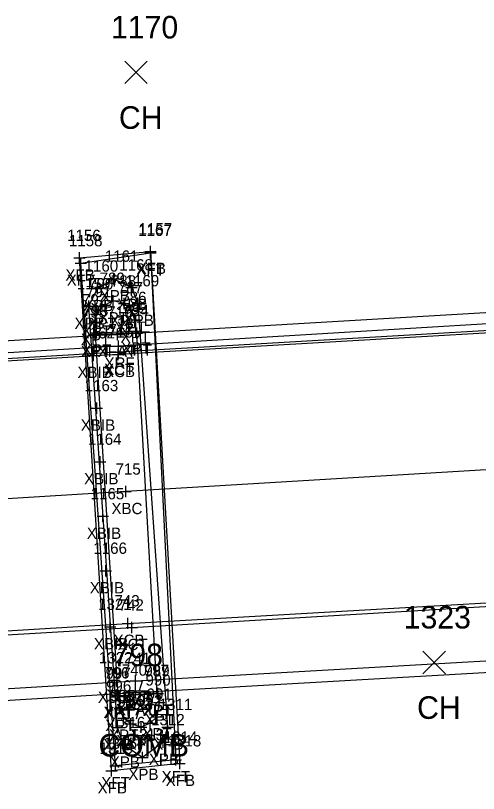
# Model space of a CAD drawing. Extents: x 1716490 to 1717645, y 888034 to 890004.
# Drawn here: x 1716987.9 to 1717028.9, y 888210.8 to 888279.7 of the extents above; entities that cross this region are included whole.
import ezdxf

# ---------------------------------------------------------------- set-up
doc = ezdxf.new("R2010")
doc.units = 0
for name, color, linetype in [('B_A', 7, 'Continuous'), ('B_I', 7, 'Continuous'), ('B_TIC', 7, 'Continuous'), ('BDC', 7, 'Continuous'), ('BELB', 7, 'Continuous'), ('BF', 7, 'Continuous'), ('BFT', 7, 'Continuous'), ('BR', 7, 'Continuous'), ('BSUBM', 7, 'Continuous'), ('L_A', 7, 'Continuous'), ('L_I', 7, 'Continuous'), ('L_TIC', 7, 'Continuous'), ('U_A', 7, 'Continuous'), ('U_I', 7, 'Continuous'), ('UP', 7, 'Continuous')]:
    doc.layers.add(name, color=color, linetype=linetype)

msp = doc.modelspace()

# ---------------------------------------------------------------- linework, layer by layer
at = {"layer": 'B_TIC'}
for p, q in [((1716993.563, 888258.21), (1716993.639, 888258.21)), ((1716999.857, 888258.656), (1716999.933, 888258.656)), ((1716999.868, 888258.793), (1716999.944, 888258.793)), ((1716993.698, 888257.744), (1716993.773, 888257.744)), ((1716996.618, 888256.374), (1716996.694, 888256.374)), ((1716995.153, 888255.5), (1716995.229, 888255.5)), ((1716998.183, 888255.6), (1716998.259, 888255.6)), ((1716996.541, 888254.414), (1716996.617, 888254.414)), ((1716997.538, 888254.168), (1716997.614, 888254.168)), ((1716998.745, 888254.197), (1716998.82, 888254.197)), ((1716994.393, 888253.93), (1716994.469, 888253.93)), ((1716995.566, 888253.926), (1716995.641, 888253.926)), ((1716998.143, 888253.584), (1716998.218, 888253.584)), ((1716995.049, 888253.239), (1716995.125, 888253.239)), ((1716998.485, 888252.722), (1716998.561, 888252.722)), ((1716994.974, 888252.512), (1716995.049, 888252.512)), ((1716994.957, 888251.44), (1716995.033, 888251.44)), ((1716995.078, 888251.568), (1716995.153, 888251.568)), ((1716996.928, 888251.433), (1716997.004, 888251.433)), ((1716998.549, 888251.731), (1716998.624, 888251.731)), ((1716998.658, 888251.565), (1716998.733, 888251.565)), ((1716997.024, 888250.409), (1716997.1, 888250.409)), ((1716994.822, 888249.583), (1716994.897, 888249.583)), ((1716997.005, 888249.663), (1716997.081, 888249.663)), ((1716997.033, 888249.858), (1716997.109, 888249.858)), ((1716995.116, 888244.912), (1716995.191, 888244.912)), ((1716995.404, 888240.168), (1716995.479, 888240.168)), ((1716997.661, 888237.527), (1716997.737, 888237.527)), ((1716995.648, 888235.339), (1716995.723, 888235.339)), ((1716995.914, 888230.512), (1716995.989, 888230.512)), ((1716997.85, 888225.861), (1716997.926, 888225.861)), ((1716996.279, 888225.548), (1716996.355, 888225.548)), ((1716998.219, 888225.489), (1716998.294, 888225.489)), ((1716996.628, 888220.815), (1716996.703, 888220.815)), ((1716998.526, 888220.762), (1716998.601, 888220.762)), ((1716998.541, 888219.726), (1716998.616, 888219.726)), ((1717000.457, 888219.692), (1717000.532, 888219.692)), ((1717000.503, 888219.658), (1717000.579, 888219.658)), ((1716996.973, 888219.484), (1716997.049, 888219.484)), ((1716997.059, 888219.449), (1716997.134, 888219.449)), ((1716997.134, 888218.322), (1716997.21, 888218.322)), ((1717000.636, 888218.845), (1717000.712, 888218.845)), ((1717000.416, 888217.591), (1717000.492, 888217.591)), ((1716997.463, 888217.465), (1716997.539, 888217.465)), ((1716998.12, 888216.963), (1716998.195, 888216.963)), ((1716999.841, 888217.026), (1716999.916, 888217.026)), ((1716996.939, 888216.631), (1716997.015, 888216.631)), ((1716999.022, 888216.666), (1716999.097, 888216.666)), ((1717001.368, 888216.681), (1717001.443, 888216.681)), ((1716997.51, 888215.08), (1716997.585, 888215.08)), ((1717000.975, 888215.331), (1717001.051, 888215.331)), ((1716999.156, 888213.995), (1716999.231, 888213.995)), ((1717002.1, 888213.787), (1717002.175, 888213.787)), ((1717002.443, 888213.46), (1717002.519, 888213.46)), ((1716996.413, 888212.8), (1716996.489, 888212.8)), ((1716996.753, 888213.25), (1716996.829, 888213.25))]:
    msp.add_line(p, q, dxfattribs=at)
for points in [[(1716999.854, 888258.156), (1716999.854, 888259.156)], [(1716999.865, 888258.293), (1716999.865, 888259.293)], [(1716993.06, 888258.21), (1716994.06, 888258.21)], [(1716993.56, 888257.71), (1716993.56, 888258.71)], [(1716993.694, 888257.244), (1716993.694, 888258.244)], [(1716999.354, 888258.656), (1717000.354, 888258.656)], [(1716999.365, 888258.793), (1717000.365, 888258.793)], [(1716993.194, 888257.744), (1716994.194, 888257.744)], [(1716996.615, 888255.874), (1716996.615, 888256.874)], [(1716996.115, 888256.374), (1716997.115, 888256.374)], [(1716998.18, 888255.1), (1716998.18, 888256.1)], [(1716994.65, 888255.5), (1716995.65, 888255.5)], [(1716995.15, 888255), (1716995.15, 888256)], [(1716997.68, 888255.6), (1716998.68, 888255.6)], [(1716996.538, 888253.914), (1716996.538, 888254.914)], [(1716998.741, 888253.697), (1716998.741, 888254.697)], [(1716994.39, 888253.43), (1716994.39, 888254.43)], [(1716995.562, 888253.426), (1716995.562, 888254.426)], [(1716996.038, 888254.414), (1716997.038, 888254.414)], [(1716997.035, 888254.168), (1716998.035, 888254.168)], [(1716997.535, 888253.668), (1716997.535, 888254.668)], [(1716998.139, 888253.084), (1716998.139, 888254.084)], [(1716998.241, 888254.197), (1716999.241, 888254.197)], [(1716993.89, 888253.93), (1716994.89, 888253.93)], [(1716995.046, 888252.739), (1716995.046, 888253.739)], [(1716995.062, 888253.926), (1716996.062, 888253.926)], [(1716997.639, 888253.584), (1716998.639, 888253.584)], [(1716994.546, 888253.239), (1716995.546, 888253.239)], [(1716994.97, 888252.012), (1716994.97, 888253.012)], [(1716997.982, 888252.722), (1716998.982, 888252.722)], [(1716998.482, 888252.222), (1716998.482, 888253.222)], [(1716994.47, 888252.512), (1716995.47, 888252.512)], [(1716994.954, 888250.94), (1716994.954, 888251.94)], [(1716995.074, 888251.068), (1716995.074, 888252.068)], [(1716996.925, 888250.933), (1716996.925, 888251.933)], [(1716998.545, 888251.231), (1716998.545, 888252.231)], [(1716998.654, 888251.065), (1716998.654, 888252.065)], [(1716994.454, 888251.44), (1716995.454, 888251.44)], [(1716994.574, 888251.568), (1716995.574, 888251.568)], [(1716996.425, 888251.433), (1716997.425, 888251.433)], [(1716998.045, 888251.731), (1716999.045, 888251.731)], [(1716998.154, 888251.565), (1716999.154, 888251.565)], [(1716997.021, 888249.909), (1716997.021, 888250.909)], [(1716994.818, 888249.083), (1716994.818, 888250.083)], [(1716996.521, 888250.409), (1716997.521, 888250.409)], [(1716997.002, 888249.163), (1716997.002, 888250.163)], [(1716997.03, 888249.358), (1716997.03, 888250.358)], [(1716994.318, 888249.583), (1716995.318, 888249.583)], [(1716996.502, 888249.663), (1716997.502, 888249.663)], [(1716996.53, 888249.858), (1716997.53, 888249.858)], [(1716995.112, 888244.412), (1716995.112, 888245.412)], [(1716994.612, 888244.912), (1716995.612, 888244.912)], [(1716995.4, 888239.668), (1716995.4, 888240.668)], [(1716994.9, 888240.168), (1716995.9, 888240.168)], [(1716997.158, 888237.527), (1716998.158, 888237.527)], [(1716997.658, 888237.027), (1716997.658, 888238.027)], [(1716995.644, 888234.839), (1716995.644, 888235.839)], [(1716995.144, 888235.339), (1716996.144, 888235.339)], [(1716995.91, 888230.012), (1716995.91, 888231.012)], [(1716995.41, 888230.512), (1716996.41, 888230.512)], [(1716996.276, 888225.048), (1716996.276, 888226.048)], [(1716997.347, 888225.861), (1716998.347, 888225.861)], [(1716997.847, 888225.361), (1716997.847, 888226.361)], [(1716998.215, 888224.989), (1716998.215, 888225.989)], [(1716995.776, 888225.548), (1716996.776, 888225.548)], [(1716997.715, 888225.489), (1716998.715, 888225.489)], [(1716996.624, 888220.315), (1716996.624, 888221.315)], [(1716998.522, 888220.262), (1716998.522, 888221.262)], [(1716996.124, 888220.815), (1716997.124, 888220.815)], [(1716998.022, 888220.762), (1716999.022, 888220.762)], [(1716996.97, 888218.984), (1716996.97, 888219.984)], [(1716997.055, 888218.949), (1716997.055, 888219.949)], [(1716998.037, 888219.726), (1716999.037, 888219.726)], [(1716998.537, 888219.226), (1716998.537, 888220.226)], [(1716999.953, 888219.692), (1717000.953, 888219.692)], [(1717000, 888219.658), (1717001, 888219.658)], [(1717000.453, 888219.192), (1717000.453, 888220.192)], [(1717000.5, 888219.158), (1717000.5, 888220.158)], [(1716996.47, 888219.484), (1716997.47, 888219.484)], [(1716996.555, 888219.449), (1716997.555, 888219.449)], [(1717000.633, 888218.345), (1717000.633, 888219.345)], [(1716996.631, 888218.322), (1716997.631, 888218.322)], [(1716997.131, 888217.822), (1716997.131, 888218.822)], [(1717000.133, 888218.845), (1717001.133, 888218.845)], [(1716997.46, 888216.965), (1716997.46, 888217.965)], [(1716999.837, 888216.526), (1716999.837, 888217.526)], [(1716999.913, 888217.591), (1717000.913, 888217.591)], [(1717000.413, 888217.091), (1717000.413, 888218.091)], [(1716996.936, 888216.131), (1716996.936, 888217.131)], [(1716996.96, 888217.465), (1716997.96, 888217.465)], [(1716997.616, 888216.963), (1716998.616, 888216.963)], [(1716998.116, 888216.463), (1716998.116, 888217.463)], [(1716999.018, 888216.166), (1716999.018, 888217.166)], [(1716999.337, 888217.026), (1717000.337, 888217.026)], [(1717001.364, 888216.181), (1717001.364, 888217.181)], [(1716996.436, 888216.631), (1716997.436, 888216.631)], [(1716998.518, 888216.666), (1716999.518, 888216.666)], [(1717000.864, 888216.681), (1717001.864, 888216.681)], [(1716997.506, 888214.58), (1716997.506, 888215.58)], [(1717000.972, 888214.831), (1717000.972, 888215.831)], [(1716997.006, 888215.08), (1716998.006, 888215.08)], [(1717000.472, 888215.331), (1717001.472, 888215.331)], [(1716999.152, 888213.495), (1716999.152, 888214.495)], [(1717002.096, 888213.287), (1717002.096, 888214.287)], [(1716996.75, 888212.75), (1716996.75, 888213.75)], [(1716998.652, 888213.995), (1716999.652, 888213.995)], [(1717001.596, 888213.787), (1717002.596, 888213.787)], [(1717001.94, 888213.46), (1717002.94, 888213.46)], [(1717002.44, 888212.96), (1717002.44, 888213.96)], [(1716995.91, 888212.8), (1716996.91, 888212.8)], [(1716996.25, 888213.25), (1716997.25, 888213.25)], [(1716996.41, 888212.3), (1716996.41, 888213.3)]]:
    msp.add_lwpolyline(points, dxfattribs=at)
at = {"layer": 'BDC'}
for points in [[(1717176.589, 888262.234), (1717176.877, 888260.812), (1717116.829, 888257.088), (1717056.7, 888253.344), (1716997.03, 888249.858), (1716936.998, 888246.313), (1716877.496, 888242.928), (1716877.301, 888244.49)], [(1717176.976, 888262.024), (1717176.866, 888260.514), (1717116.827, 888256.946), (1717056.83, 888253.148), (1716997.002, 888249.663), (1716937.062, 888246.095), (1716877.423, 888242.56)], [(1716878.985, 888212.69), (1716878.754, 888218.609), (1716938.217, 888221.984), (1716998.215, 888225.489), (1717058.321, 888229.074), (1717118.074, 888232.734), (1717177.978, 888236.214), (1717178.104, 888235.65), (1717178.633, 888230.445)], [(1716878.76, 888218.785), (1716938.254, 888222.245), (1716997.847, 888225.861), (1717058.278, 888229.335), (1717118.147, 888232.862), (1717177.913, 888236.497)]]:
    msp.add_lwpolyline(points, dxfattribs=at)
at = {"layer": 'BELB'}
msp.add_lwpolyline([(1717176.82, 888248.242), (1717117.599, 888244.664), (1717057.58, 888241.128), (1716997.658, 888237.527), (1716937.868, 888233.85), (1716878.264, 888230.514)], dxfattribs=at)
at = {"layer": 'BF'}
for points in [[(1717176.589, 888262.234), (1717116.538, 888258.636), (1717056.61, 888254.944), (1716996.925, 888251.433), (1716937.102, 888247.945), (1716877.301, 888244.49)], [(1716878.985, 888212.69), (1716938.928, 888216.097), (1716998.537, 888219.726), (1717058.79, 888223.18), (1717118.388, 888226.857), (1717178.633, 888230.445)]]:
    msp.add_lwpolyline(points, dxfattribs=at)
at = {"layer": 'BFT'}
for points in [[(1716993.56, 888258.21), (1716999.865, 888258.793), (1717002.44, 888213.46), (1716996.41, 888212.8)], [(1716996.41, 888212.8), (1716993.56, 888258.21)], [(1716993.694, 888257.744), (1716999.854, 888258.656), (1717002.096, 888213.787), (1716996.75, 888213.25)], [(1716996.75, 888213.25), (1716993.694, 888257.744)]]:
    msp.add_lwpolyline(points, dxfattribs=at)
at = {"layer": 'BR'}
for points in [[(1717175.997, 888261.982), (1717175.88, 888261.141), (1717117.062, 888257.612), (1717056.557, 888253.997), (1716997.021, 888250.409), (1716936.966, 888246.784), (1716878.141, 888243.386), (1716877.962, 888244.411)], [(1716879.623, 888212.902), (1716879.679, 888213.775), (1716938.703, 888217.127), (1716998.522, 888220.762), (1717058.504, 888224.208), (1717118.654, 888227.867), (1717177.581, 888231.531), (1717177.859, 888230.636)]]:
    msp.add_lwpolyline(points, dxfattribs=at)
at = {"layer": 'BSUBM'}
for points in [[(1716994.39, 888253.93), (1716995.15, 888255.5), (1716996.615, 888256.374), (1716998.18, 888255.6), (1716998.741, 888254.197), (1717001.364, 888216.681), (1717000.972, 888215.331), (1716999.152, 888213.995), (1716997.506, 888215.08), (1716996.936, 888216.631)], [(1716998.545, 888251.731), (1716998.482, 888252.722), (1716998.139, 888253.584), (1716997.535, 888254.168), (1716996.538, 888254.414), (1716995.562, 888253.926), (1716995.046, 888253.239), (1716994.97, 888252.512), (1716995.074, 888251.568)], [(1716996.936, 888216.631), (1716994.39, 888253.93)], [(1716998.654, 888251.565), (1716994.954, 888251.44), (1716996.97, 888219.484), (1717000.453, 888219.692)], [(1716995.074, 888251.568), (1716998.545, 888251.731)], [(1717000.453, 888219.692), (1716998.654, 888251.565)], [(1717000.5, 888219.658), (1717000.633, 888218.845), (1717000.413, 888217.591), (1716999.837, 888217.026), (1716999.018, 888216.666), (1716998.116, 888216.963), (1716997.46, 888217.465), (1716997.131, 888218.322), (1716997.055, 888219.449)], [(1716997.055, 888219.449), (1717000.5, 888219.658)]]:
    msp.add_lwpolyline(points, dxfattribs=at)
at = {"layer": 'L_TIC'}
for points in [[(1716997.572, 888273.643), (1716999.572, 888275.643)], [(1716999.572, 888273.643), (1716997.572, 888275.643)], [(1717023.977, 888221.403), (1717025.977, 888223.403)], [(1717025.977, 888221.403), (1717023.977, 888223.403)]]:
    msp.add_lwpolyline(points, dxfattribs=at)
at = {"layer": 'UP'}
for p, q in [((1716999.111, 888220.731), (1716998.861, 888219.898)), ((1716998.027, 888218.231), (1716998.027, 888219.898)), ((1716998.027, 888219.898), (1716999.694, 888219.898)), ((1716999.694, 888219.898), (1716999.694, 888218.231)), ((1716998.861, 888219.065), (1716998.861, 888219.065)), ((1716999.694, 888218.231), (1716998.027, 888218.231)), ((1716998.611, 888217.398), (1716998.861, 888218.231))]:
    msp.add_line(p, q, dxfattribs=at)
msp.add_circle((1716998.861, 888219.065), 0.833, dxfattribs=at)

# ---------------------------------------------------------------- texts
at = {"layer": 'B_A'}
for s, p in [('XFT', (1716998.598, 888256.656)), ('XFB', (1716998.625, 888256.793)), ('XFB', (1716992.32, 888256.21)), ('XFT', (1716992.439, 888255.744)), ('XPB', (1716995.351, 888254.374)), ('XPB', (1716993.886, 888253.5)), ('XPB', (1716996.916, 888253.6)), ('XPT', (1716995.258, 888252.414)), ('XPB', (1716993.126, 888251.93)), ('XPT', (1716994.283, 888251.926)), ('XPT', (1716996.255, 888252.168)), ('XPB', (1716997.477, 888252.197)), ('XPT', (1716993.766, 888251.239)), ('XPT', (1716996.86, 888251.584)), ('XPT', (1716993.691, 888250.512)), ('XPT', (1716997.202, 888250.722)), ('XPT', (1716993.795, 888249.568)), ('XPT', (1716997.266, 888249.731)), ('XPT', (1716997.375, 888249.565)), ('XPT', (1716993.674, 888249.44)), ('XFAT', (1716995.181, 888249.433)), ('XRF', (1716995.781, 888248.409)), ('XBIB', (1716993.389, 888247.583)), ('XCB', (1716995.738, 888247.663)), ('XCT', (1716995.75, 888247.858)), ('XBIB', (1716993.683, 888242.912)), ('XBIB', (1716993.971, 888238.168)), ('XBC', (1716996.394, 888235.527)), ('XBIB', (1716994.215, 888233.339)), ('XBIB', (1716994.481, 888228.512)), ('XBIB', (1716994.847, 888223.548)), ('XCB', (1716996.583, 888223.861)), ('XCT', (1716996.936, 888223.489)), ('XBIB', (1716995.195, 888218.815)), ('XRF', (1716997.282, 888218.762)), ('XPT', (1716995.69, 888217.484)), ('XPT', (1716995.776, 888217.449)), ('XFAT', (1716996.793, 888217.726)), ('XPT', (1716999.174, 888217.692)), ('XPT', (1716999.22, 888217.658)), ('XPT', (1716999.353, 888216.845)), ('XPT', (1716995.851, 888216.322)), ('XPT', (1716996.18, 888215.465)), ('XPT', (1716999.133, 888215.591)), ('XPB', (1716995.672, 888214.631)), ('XPT', (1716996.837, 888214.963)), ('XPT', (1716997.739, 888214.666)), ('XPT', (1716998.558, 888215.026)), ('XPB', (1717000.101, 888214.681)), ('XPB', (1716996.243, 888213.08)), ('XPB', (1716999.708, 888213.331)), ('XPB', (1716997.889, 888211.995)), ('XFT', (1717000.84, 888211.787)), ('XFT', (1716995.494, 888211.25)), ('XFB', (1717001.2, 888211.46)), ('XFB', (1716995.17, 888210.8))]:
    msp.add_text(s, height=1, dxfattribs=at).set_placement(p)
at = {"layer": 'B_I'}
for s, p in [('1167', (1716998.767, 888260.156)), ('1157', (1716998.802, 888260.293)), ('1156', (1716992.469, 888259.71)), ('1158', (1716992.631, 888259.244)), ('1161', (1716995.812, 888257.874)), ('1160', (1716994.02, 888257)), ('1168', (1716997.093, 888257.1)), ('789', (1716995.353, 888255.914)), ('1159', (1716993.323, 888255.43)), ('790', (1716994.338, 888255.426)), ('788', (1716996.354, 888255.668)), ('787', (1716996.958, 888255.084)), ('1169', (1716997.651, 888255.697)), ('791', (1716994.148, 888254.739)), ('792', (1716993.789, 888254.012)), ('786', (1716997.273, 888254.222)), ('793', (1716993.893, 888253.068)), ('785', (1716997.364, 888253.231)), ('794', (1716997.473, 888253.065)), ('795', (1716993.772, 888252.94)), ('719', (1716996.023, 888252.933)), ('718', (1716996.123, 888251.909)), ('1162', (1716993.732, 888251.083)), ('716', (1716996.076, 888251.163)), ('717', (1716996.132, 888251.358)), ('1163', (1716994.026, 888246.412)), ('1164', (1716994.314, 888241.668)), ('715', (1716996.76, 888239.027)), ('1165', (1716994.557, 888236.839)), ('1166', (1716994.796, 888232.012)), ('1321', (1716995.213, 888227.048)), ('743', (1716996.666, 888227.361)), ('742', (1716997.034, 888226.989)), ('1322', (1716995.278, 888222.315)), ('741', (1716997.625, 888222.262)), ('796', (1716995.761, 888220.984)), ('997', (1716995.874, 888220.949)), ('740', (1716997.313, 888221.226)), ('797', (1716999.272, 888221.192)), ('989', (1716999.315, 888221.158)), ('990', (1716999.408, 888220.345)), ('996', (1716995.922, 888219.822)), ('995', (1716996.278, 888218.965)), ('991', (1716999.515, 888219.091)), ('1317', (1716995.873, 888218.131)), ('994', (1716996.935, 888218.463)), ('993', (1716997.837, 888218.166)), ('992', (1716998.656, 888218.526)), ('1311', (1717000.585, 888218.181)), ('1316', (1716996.416, 888216.58)), ('1312', (1716999.909, 888216.831)), ('1313', (1716998.089, 888215.495)), ('1314', (1717001.033, 888215.287)), ('1315', (1716995.687, 888214.75)), ('1318', (1717001.377, 888214.96)), ('1319', (1716995.343, 888214.3))]:
    msp.add_text(s, height=1, dxfattribs=at).set_placement(p)
at = {"layer": 'L_A'}
for p in [(1716997.06, 888269.643), (1717023.465, 888217.403)]:
    msp.add_text('CH', height=2, dxfattribs=at).set_placement(p)
at = {"layer": 'L_I'}
for s, p in [('1170', (1716996.36, 888277.643)), ('1323', (1717022.284, 888225.403))]:
    msp.add_text(s, height=2, dxfattribs=at).set_placement(p)
at = {"layer": 'U_A'}
msp.add_text('COMB', height=2, dxfattribs=at).set_placement((1716995.247, 888214.065))
at = {"layer": 'U_I'}
msp.add_text('798', height=2, dxfattribs=at).set_placement((1716996.499, 888222.065))

doc.saveas('drawing.dxf')
